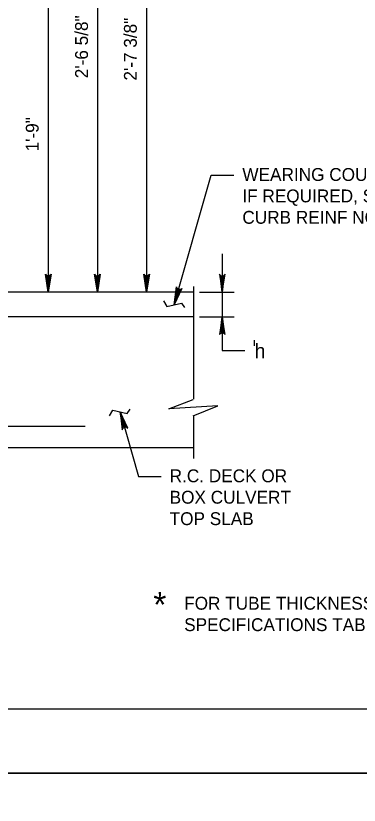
# Model space of a CAD drawing. Extents: x 641054 to 641910, y 298137 to 299325.
# Drawn here: x 641328.5 to 641408.6, y 298723.9 to 298908.1 of the extents above; entities that cross this region are included whole.
import ezdxf

# ---------------------------------------------------------------- set-up
doc = ezdxf.new("R2010")
doc.units = 0
for name, color, linetype in [('1', 7, 'Continuous'), ('2', 7, 'Continuous'), ('4', 7, 'Continuous'), ('PLT-BNDY', 7, 'Continuous')]:
    doc.layers.add(name, color=color, linetype=linetype)

msp = doc.modelspace()

# ---------------------------------------------------------------- linework, layer by layer
at = {"layer": '1'}
for p, q in [((641347.51, 298978.15), (641347.51, 298843.61)), ((641336.03, 298963.63), (641336.03, 298843.61)), ((641358.98, 298963.63), (641358.98, 298843.61)), ((641365.46, 298840.64), (641374.07, 298870.91)), ((641374.07, 298870.91), (641379.35, 298870.91)), ((641376.65, 298852.52), (641376.65, 298829.98)), ((641369.97, 298844.93), (641369.97, 298821.48)), ((641371.31, 298843.61), (641379.43, 298843.61)), ((641371.31, 298837.87), (641379.43, 298837.87)), ((641376.65, 298829.98), (641381.93, 298829.98)), ((641369.97, 298821.48), (641369.97, 298818.61)), ((641352.8, 298815.71), (641357.1, 298800.58)), ((641369.97, 298814.79), (641369.97, 298804.83)), ((641357.1, 298800.58), (641362.38, 298800.58))]:
    msp.add_line(p, q, dxfattribs=at)
msp.add_lwpolyline([(641369.9, 298814.76), (641375.64, 298817.08), (641364.16, 298816.39), (641369.9, 298818.58)], dxfattribs=at)
at = {"layer": '2'}
for p, q in [((641369.97, 298843.61), (641254.66, 298843.61)), ((641369.97, 298837.87), (641188.68, 298837.87)), ((641384.2, 298831.05), (641384.2, 298832.44)), ((641369.97, 298807.27), (641188.68, 298807.27)), ((641094.49, 298746.38), (641880.49, 298746.38))]:
    msp.add_line(p, q, dxfattribs=at)
for points in [[(641336.53, 298847.59), (641336.24, 298847.44), (641336.03, 298843.61), (641336.53, 298847.59), (641336.7, 298847.79), (641336.03, 298843.61), (641335.84, 298847.43), (641335.56, 298847.57), (641336.03, 298843.61), (641335.37, 298847.79), (641335.56, 298847.57)], [(641348, 298847.59), (641347.72, 298847.44), (641347.51, 298843.61), (641348, 298847.59), (641348.18, 298847.79), (641347.51, 298843.61), (641347.32, 298847.43), (641347.03, 298847.57), (641347.51, 298843.61), (641346.84, 298847.79), (641347.03, 298847.57)], [(641359.48, 298847.59), (641359.19, 298847.44), (641358.98, 298843.61), (641359.48, 298847.59), (641359.65, 298847.79), (641358.98, 298843.61), (641358.79, 298847.43), (641358.51, 298847.57), (641358.98, 298843.61), (641358.32, 298847.79), (641358.51, 298847.57)], [(641376.15, 298847.59), (641376.44, 298847.44), (641376.65, 298843.61), (641376.15, 298847.59), (641375.98, 298847.79), (641376.65, 298843.61), (641376.84, 298847.43), (641377.12, 298847.57), (641376.65, 298843.61), (641377.31, 298847.79), (641377.12, 298847.57)], [(641367.03, 298844.33), (641366.71, 298844.26), (641365.46, 298840.64), (641367.03, 298844.33), (641367.25, 298844.48), (641365.46, 298840.64), (641366.33, 298844.37), (641366.09, 298844.58), (641365.46, 298840.64), (641365.97, 298844.84), (641366.09, 298844.58)], [(641362.98, 298841.62), (641363.76, 298840.26), (641367.13, 298841.04), (641367.84, 298840.04)], [(641377.15, 298833.9), (641376.86, 298834.05), (641376.65, 298837.87), (641377.15, 298833.9), (641377.32, 298833.7), (641376.65, 298837.87), (641376.46, 298834.05), (641376.17, 298833.91), (641376.65, 298837.87), (641375.98, 298833.7), (641376.17, 298833.91)], [(641350.31, 298814.74), (641351.1, 298816.1), (641354.46, 298815.31), (641355.18, 298816.31)], [(641354.36, 298812.02), (641354.05, 298812.09), (641352.8, 298815.71), (641354.36, 298812.02), (641354.59, 298811.88), (641352.8, 298815.71), (641353.66, 298811.98), (641353.43, 298811.77), (641352.8, 298815.71), (641353.3, 298811.51), (641353.43, 298811.77)]]:
    msp.add_lwpolyline(points, dxfattribs=at)
at = {"layer": '4'}
msp.add_line((641344.66, 298812.27), (641252.75, 298812.27), dxfattribs=at)
at = {"layer": 'PLT-BNDY'}
for points in [[(641054.49, 299325.38), (641895.49, 299325.38), (641895.49, 298731.38), (641054.49, 298731.38)], [(641054.49, 298731.38), (641895.49, 298731.38), (641895.49, 298137.38), (641054.49, 298137.38)]]:
    msp.add_lwpolyline(points, close=True, dxfattribs=at)

# ---------------------------------------------------------------- texts
at = {"layer": '2'}
for s, p in [('2\'-6 5/8"', (641345.32, 298893.53)), ('2\'-7 3/8"', (641356.71, 298892.98)), ('1\'-9"', (641333.81, 298876.46))]:
    msp.add_text(s, height=3, rotation=90, dxfattribs=at).set_placement(p)
for s, height, p in [('WEARING COURSE (h )', 3.0001, (641381.35, 298869.57)), ('IF REQUIRED, SEE', 3.0001, (641381.35, 298864.57)), ('CURB REINF NOTE 1', 3.0001, (641381.35, 298859.57)), ('h', 3.4, (641384.2, 298828.19)), ('R.C. DECK OR', 3.0001, (641364.38, 298799.25)), ('BOX CULVERT', 3.0001, (641364.38, 298794.25)), ('TOP SLAB', 3, (641364.38, 298789.25)), ('*', 5.88, (641360.56, 298767.75)), ('FOR TUBE THICKNESS, SEE TUBE RAIL', 3, (641367.77, 298769.51)), ('SPECIFICATIONS TABLE ON BC-706M.', 3, (641367.77, 298764.51))]:
    msp.add_text(s, height=height, dxfattribs=at).set_placement(p)

doc.saveas('drawing.dxf')
